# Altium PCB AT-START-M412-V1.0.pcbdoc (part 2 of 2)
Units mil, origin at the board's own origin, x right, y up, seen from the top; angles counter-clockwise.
Board outline 4079.45 x 3617.4 mil, 2 copper layers (Top Layer, Bottom Layer); 111 components, 104 nets, 441 pads, 691 vias.
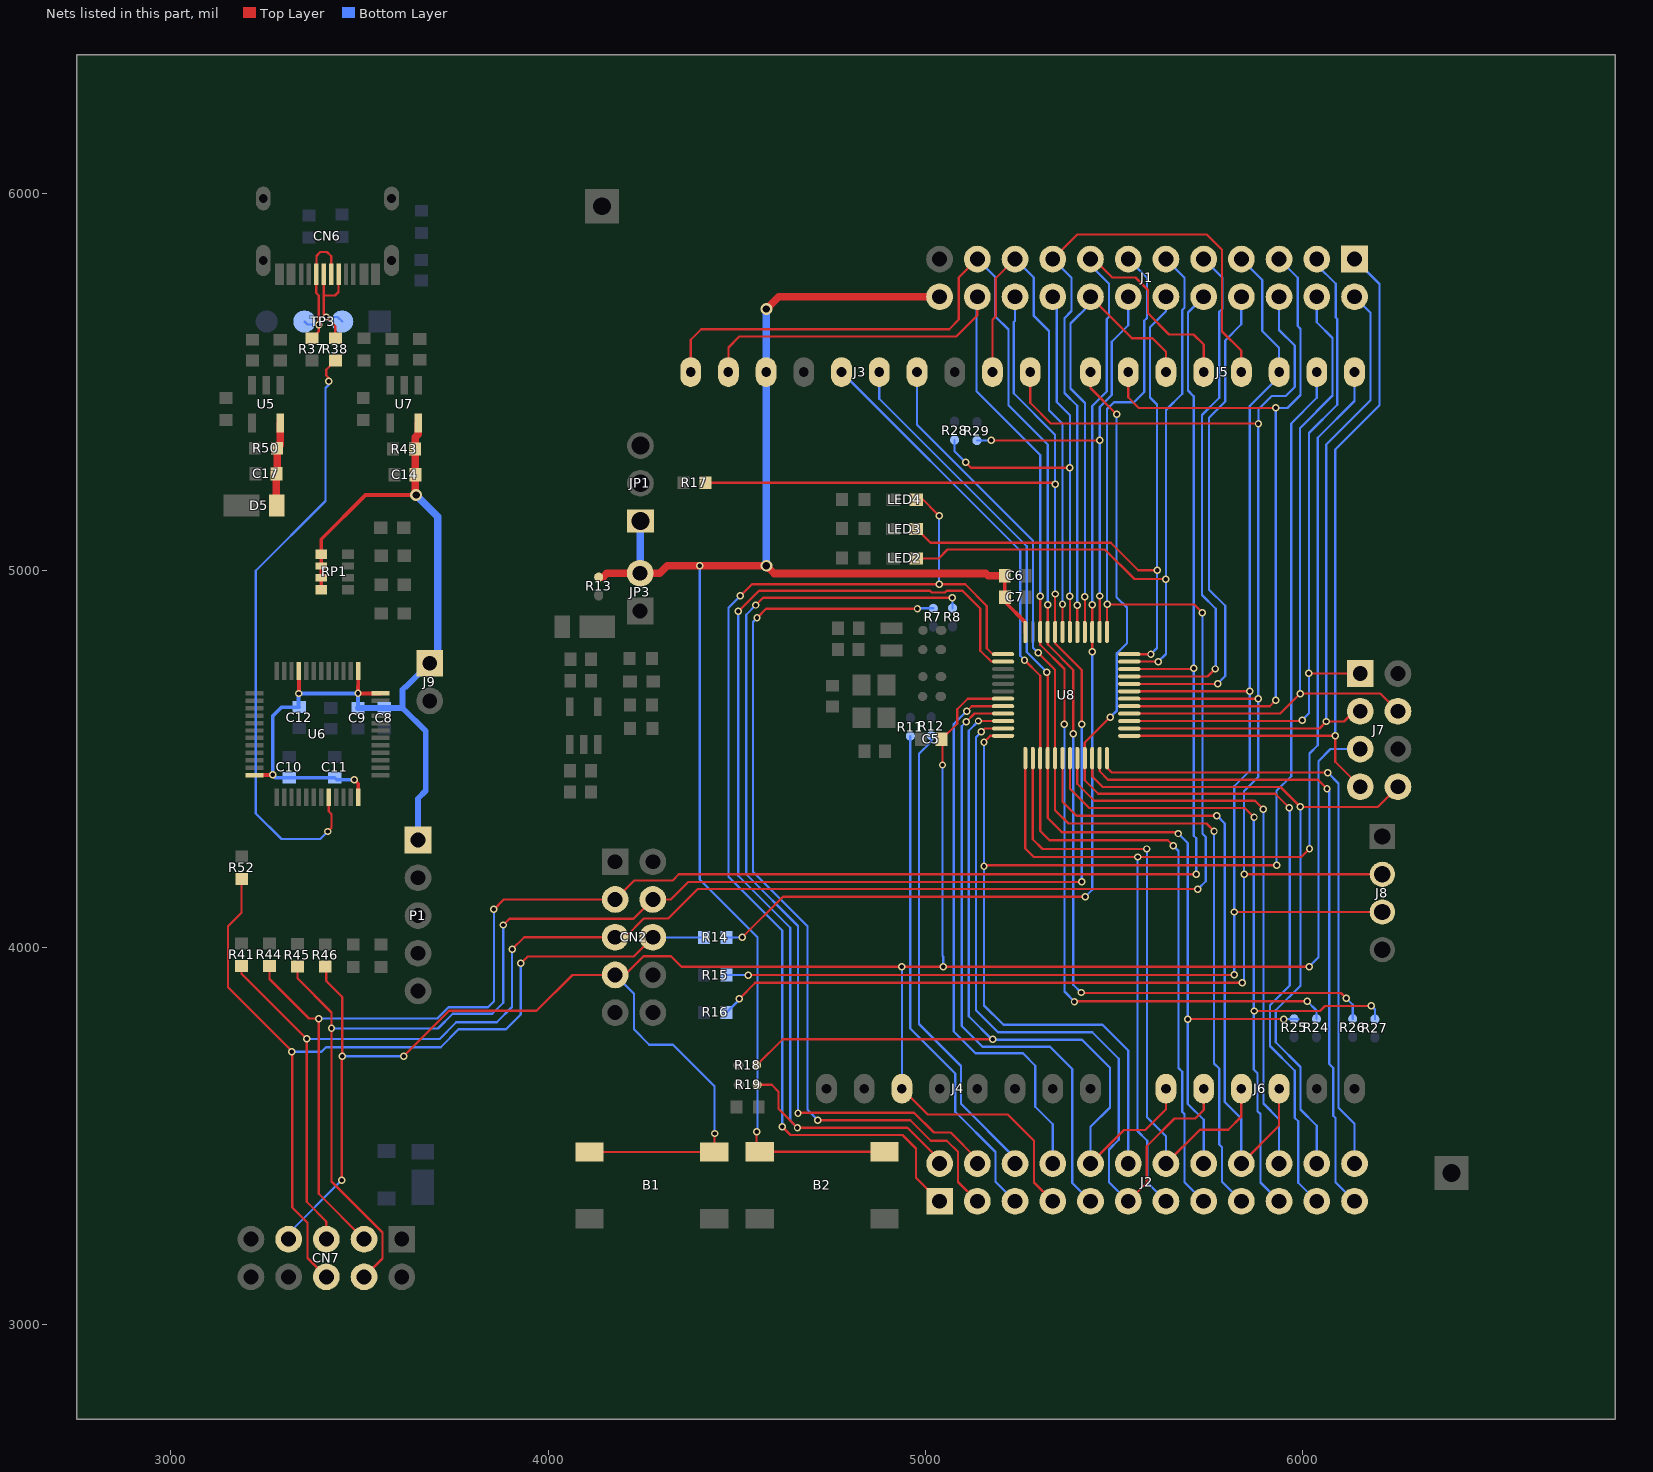
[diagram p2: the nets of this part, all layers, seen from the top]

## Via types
v1: diameter 19.68, hole 11.81, Top Layer to Bottom Layer, 340 vias
v2: diameter 19.7, hole 11.81, Top Layer to Bottom Layer, 266 vias
v3: diameter 19.7, hole 11.8, Top Layer to Bottom Layer, 67 vias
v4: diameter 31.5, hole 19.68, Top Layer to Bottom Layer, 18 vias

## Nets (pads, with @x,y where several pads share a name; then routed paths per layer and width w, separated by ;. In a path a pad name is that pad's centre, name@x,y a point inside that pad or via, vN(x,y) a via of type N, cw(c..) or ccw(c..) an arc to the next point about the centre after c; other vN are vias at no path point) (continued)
M-USB_DM: R38.2 U6.32 | length 1617.9
  Top Layer w6: v2(3415.92,4307.82) 3425.78,4317.68 3425.78,4353.69 3418.1,4361.38 U6.32@3418.1,4398.38 ; v2(3417.92,5501.82) 3417.92,5510.87 3411.92,5516.87 3411.92,5532.16 R38.2@3435.92,5556.16
  Bottom Layer w6: v2(3415.92,4307.82) 3395.92,4287.82 3292.9,4287.82 3225.1,4355.61 3225.1,4998.99 3409.92,5183.82 3409.92,5483.82 3417.92,5491.82 v2(3417.92,5501.82)
M-USB_DP: 
NRST/PF2: B1.1 B1.2 C5.2 CN2.7 CN7.7 J2.7 J4.3 J7.5 R46.2 U8.7 | length 6851
  Top Layer w6: R46.2@3409.1,3947.03 3412.1,3944.03 3412.1,3911.15 3453.92,3869.33 v2(3453.92,3712.19) 3452.74,3711.01 v2(3452.74,3383.56) ; v1(3616.76,3711.99) 3737.05,3832.28 3969.28,3832.28 4064.53,3927.53 CN2.7@4177.67,3927.53 4203.13,3927.53 4252.77,3977.17 4326.06,3977.17 4353.93,3949.29 v1@4938.05,3949.29 ; B1.1@4110.01,3458.22 B1.2@4440.71,3458.22 4441.21,3458.72 v3(4441.21,3507.15) ; J4.3@4937.93,3625.82 5006.53,3557.21 5218.78,3557.21 5287.94,3488.05 5287.94,3377.38 J2.7@5337.93,3327.39 ; v1(4937.93,3949.17) v1@4938.05,3949.29 ; v3(5045.56,4484.05) 5045.56,4549.51 C5.2@5043.05,4552.03 5084.66,4593.63 5084.66,4632.06 5112.4,4659.79 U8.7@5206.24,4659.79 ; v1@6013.68,3949.29 v3(5047.61,3949.29) v1@4938.05,3949.29
  Bottom Layer w6: CN7.7@3312.1,3227.03 3312.1,3242.91 v2(3452.74,3383.56) ; v2(3453.92,3712.19) 3616.56,3712.19 v1(3616.76,3711.99) ; CN2.7@4177.67,3927.53 4227.41,3877.79 4227.41,3783.2 4268.13,3742.48 4330.94,3742.48 4441.21,3632.2 v3(4441.21,3507.15) ; J4.3@4937.93,3625.82 v1(4937.93,3949.17) ; v3(5045.56,4484.05) 5045.56,3978.74 5047.82,3976.48 5047.82,3949.29 v3(5047.61,3949.29) ; v1(6017.36,3949.51) 6042.24,3974.39 6042.24,4494.23 6074.39,4526.39 J7.5@6152.93,4526.39
PA0: J2.10 J6.1 R18.1 U8.10 | length 2535.9
  Top Layer w6: R18.1@4552.67,3688.08 4621.93,3757.34 v3(5178.41,3757.34) ; v1(5140.91,4600.69) U8.10@5206.24,4600.69 ; J2.10@5437.93,3427.39 5526.91,3516.37 5583.1,3516.37 5637.93,3571.19 J6.1@5637.93,3625.82
  Bottom Layer w6: v1(5140.91,4600.69) 5114.9,4574.68 5114.9,3818.16 5178.05,3755.01 v3@5178.41,3755.38 ; v3(5178.41,3757.34) v3@5178.41,3755.38 ; J2.10@5437.93,3427.39 5437.93,3524.74 5489.42,3576.23 5489.42,3681.18 5415.22,3755.38 v3@5178.41,3755.38
PA1: J2.11 J6.2 U8.11 | length 2060.1
  Top Layer w6: v1(5148.24,4571.84) 5157.39,4580.99 U8.11@5206.24,4580.99 ; J2.11@5537.93,3327.39 5587.23,3376.7 5587.23,3473.4 5660.76,3546.92 5715.38,3546.92 5737.93,3569.46 J6.2@5737.93,3625.82
  Bottom Layer w6: v1(5148.24,4571.84) 5134.38,4557.98 5134.38,3833.78 5192.69,3775.48 5442.56,3775.48 5513.01,3705.02 5513.01,3490.3 5487.21,3464.5 5487.21,3378.11 J2.11@5537.93,3327.39
PA2: J2.12 J5.2 U8.12 | length 3615.6
  Top Layer w6: v1(5155.54,4544.83) 5172,4561.29 U8.12@5206.24,4561.29 ; v1(5155.64,4216.06) 5158.01,4218.43 v1(5931.14,4218.43)
  Bottom Layer w6: v1(5155.54,4544.83) v1@5155.54,4216.06 ; v1(5155.64,4216.06) v1@5155.54,4216.06 ; J2.12@5537.93,3427.39 5537.93,3727.28 5470.06,3795.15 5207.02,3795.15 5155.54,3846.64 v1@5155.54,4216.06 ; v1(5931.14,4218.43) 5931.14,4415.58 5970.01,4454.45 5970.01,5389.55 6037.93,5457.47 J5.2@6037.93,5525.82
PA3: J2.13 J5.1 U8.13 | length 3269.1
  Top Layer w6: U8.13@5265.24,4502.29 5265.24,4262.51 5287.79,4239.96 v1@5562.51,4239.96 ; v1(5562.69,4240.14) v1@5562.51,4239.96 ; v1(6018.57,4262.12) 5996.41,4239.96 v1@5562.51,4239.96
  Bottom Layer w6: v1(5562.69,4240.14) 5562.47,4239.92 5562.47,3513.58 5588.15,3487.9 5588.15,3377.18 J2.13@5637.93,3327.39 ; v1(6018.57,4262.12) 6018.57,4514.82 6040.14,4536.38 6040.14,5351.42 6137.93,5449.2 J5.1@6137.93,5525.82
PA4: J2.14 J6.3 U8.14 | length 1708.5
  Top Layer w6: U8.14@5284.94,4502.29 5284.94,4287.26 5310.73,4261.47 v1(5587.21,4261.47) ; J2.14@5637.93,3427.39 5727.92,3517.39 5803.28,3517.39 5837.93,3552.03 J6.3@5837.93,3625.82
  Bottom Layer w6: v1(5587.21,4261.47) 5587.68,4261.01 5587.68,3549.98 5637.93,3499.74 J2.14@5637.93,3427.39
PA5: J2.15 J3.6 U8.15 | length 2779.8
  Top Layer w6: v1(5262.99,4762.21) 5304.64,4720.55 U8.15@5304.64,4502.29 5304.64,4309.03 5329.11,4284.57 5642.7,4284.57 v1(5657.69,4269.58)
  Bottom Layer w6: J3.6@4777.93,5525.82 5251.54,5052.21 5251.54,4773.66 v1(5262.99,4762.21) ; v1(5657.69,4269.58) 5671.38,4255.89 5671.38,3680.63 5681.12,3670.88 5681.12,3564.97 5687.43,3558.67 5687.43,3377.89 J2.15@5737.93,3327.39
PA6: J2.16 J3.5 R25.1 U8.16 | length 2926.7
  Top Layer w6: v1(5322.25,4730.35) 5324.34,4728.26 U8.16@5324.34,4502.29 5324.34,4343.73 5361.93,4306.14 5667.09,4306.14 v1(5670.82,4302.41) ; v3(5696.26,3810.24) 5696.43,3810.42 v3(5949.99,3810.42)
  Bottom Layer w6: J3.5@4877.93,5525.82 4877.93,5455.38 5268.99,5064.32 5268.99,4783.61 v1(5322.25,4730.35) ; v1(5670.82,4302.41) 5695.62,4277.61 v3@5695.62,3810.65 ; v3(5696.26,3810.24) 5696.02,3810.24 v3@5695.62,3810.65 ; J2.16@5737.93,3427.39 5737.93,3543.27 5695.62,3585.58 v3@5695.62,3810.65 ; v3(5949.99,3810.42) 5988.44,3810.42 R25.1@5988.61,3810.24
PA7: J2.17 J3.4 U8.17 | length 2769
  Top Layer w6: v1(5299.64,4781.17) 5344.04,4736.77 U8.17@5344.04,4502.29 5344.04,4364.42 5379.71,4328.75 5745.63,4328.75 v1(5765.44,4308.94)
  Bottom Layer w6: J3.4@4977.93,5525.82 4977.93,5386.12 5285.71,5078.34 5285.71,4795.1 v1(5299.64,4781.17) ; v1(5765.44,4308.94) 5765.44,3692.91 5778.99,3679.36 5778.99,3478.08 5786.43,3470.64 5786.43,3378.89 J2.17@5837.93,3327.39
PA8: J1.5 J5.7 U8.29 | length 2103.5
  Top Layer w6: J5.7@5537.93,5525.82 5537.93,5458.76 5565.91,5430.77 v1(5929.53,5430.77) ; U8.29@5540.84,4640.09 5913.32,4640.09 v1(5929.04,4655.82)
  Bottom Layer w6: v1(5929.04,4655.82) 5929.04,5430.28 v1(5929.53,5430.77) 5960.36,5430.77 5994.76,5465.17 5994.76,5640.27 5987.32,5647.71 5987.32,5776.08 J1.5@5937.91,5825.49
PA9/USART1_TX: J1.6 J3.1 J8.2 R16.1 U8.30 | length 4727.5
  Top Layer w6: v3(4507.15,3864.57) 4549.44,3906.86 5840.33,3906.86 v1(5840.33,3906.52) ; J3.1@5277.93,5525.82 5277.93,5444.15 5332.77,5389.3 v1(5883.24,5389.3) ; U8.30@5540.84,4659.79 5882.41,4659.79 v1(5882.65,4660.03) ; v3(5845.04,4194.37) J8.2@6211.54,4194.37
  Bottom Layer w6: R16.1@4473.12,3828.11 v3@4503.24,3858.23 ; v1(5840.33,3906.52) 5844.99,3911.18 v3(5845.04,4194.37) 5844.99,4414.48 5882.65,4452.14 v1(5882.65,4660.03) 5882.65,5388.71 v1(5883.24,5389.3) 5883.24,5427.11 5918.5,5462.37 5955.89,5462.37 5979.46,5485.94 5979.46,5596.05 5937.91,5637.6 J1.6@5937.91,5725.49
PA10/USART1_RX: J1.7 J5.3 J8.3 R15.1 U8.31 | length 4046.6
  Top Layer w6: v1(4530.17,3927.07) 5818.51,3927.07 v1(5818.99,3927.55) ; U8.31@5540.84,4679.39 5859.69,4679.39 v1(5859.85,4679.55) ; v3@5819.24,4094.37 J8.3@6211.54,4094.37
  Bottom Layer w6: R15.1@4472.76,3927.07 v1(4530.17,3927.07) ; v1(5818.99,3927.55) v3@5818.99,4094.33 ; v3(5819.2,4094.33) v3@5818.99,4094.33 ; J1.7@5837.91,5825.49 5893.48,5769.93 5893.48,5634.72 5937.93,5590.27 J5.3@5937.93,5525.82 5937.93,5513.63 5859.85,5435.55 v1(5859.85,4679.55) 5859.85,4468.91 5818.99,4428.06 v3@5818.99,4094.33
PA11: J1.8 U8.32 | length 1321.6
  Top Layer w6: U8.32@5540.84,4699.09 5774.09,4699.09 v1(5774.78,4699.78)
  Bottom Layer w6: v1(5774.78,4699.78) 5795.04,4720.05 5795.04,4906.01 5752.13,4948.92 5752.13,5404.96 5795.04,5447.87 5795.04,5609.74 5837.91,5652.61 J1.8@5837.91,5725.49
PA12: J1.9 U8.33 | length 1381.3
  Top Layer w6: U8.33@5540.84,4718.79 5748.35,4718.79 v1(5768.23,4738.67)
  Bottom Layer w6: J1.9@5737.91,5825.49 5787.67,5775.73 5787.67,5693.85 5779.51,5685.69 5779.51,5458 5733.53,5412.02 5733.53,4934.98 5770.01,4898.49 5770.01,4740.45 v1@5768.29,4738.73
PA13/SWDIO: CN2.3 CN7.3 J1.10 R44.2 U8.34 | length 5200
  Top Layer w6: R44.2@3261.3,3951.41 3261.3,3916.44 3365.92,3811.82 v2(3391.92,3811.82) 3391.92,3347.2 CN7.3@3512.1,3227.03 ; v2(3856.23,4101.13) 3882.63,4127.53 CN2.3@4177.67,4127.53 4228.3,4178.15 4330.17,4178.15 4346.4,4194.38 v1(5718.32,4194.38) ; U8.34@5540.84,4738.49 5709.8,4738.49 v1(5711.64,4740.33)
  Bottom Layer w6: v2(3391.92,3811.82) 3705.89,3811.82 3735.97,3841.9 3840.32,3841.9 3856.23,3857.81 v2(3856.23,4101.13) ; v1@5711.58,4740.38 5711.58,5461.35 5696.16,5476.77 5696.16,5683.74 J1.10@5737.91,5725.49 ; v1(5711.64,4740.33) 5711.64,4296.69 5718.32,4290 v1(5718.32,4194.38)
PA14/SWCLK: CN2.5 CN7.5 J1.13 R41.2 U8.37 | length 5525.2
  Top Layer w6: R41.2@3187.3,3951.41 3187.3,3930.44 v2(3359.92,3757.82) 3359.92,3326.08 3412.1,3273.9 CN7.5@3412.1,3227.03 ; v2(3904.53,3995.38) 3936.68,4027.53 CN2.5@4177.67,4027.53 4204.22,4027.53 4253.74,4077.05 4318.57,4077.05 4396.59,4155.07 v1@5722.61,4155.07 ; U8.37@5481.84,4836.89 v1(5481.84,4909.82) 5712.77,4909.82 v1(5734.67,4887.91)
  Bottom Layer w6: v2(3359.92,3757.82) 3712.75,3757.82 3756.74,3801.81 3863.54,3801.81 3904.53,3842.8 v2(3904.53,3995.38) ; v1(5481.84,4909.82) 5481.84,5427.57 5499.95,5445.69 5553.32,5445.69 5580.44,5472.8 5580.44,5661.67 5587.65,5668.88 5587.65,5775.76 J1.13@5537.91,5825.49 ; v1(5722.61,4155.05) 5743.17,4175.61 5743.17,4293.27 5734.67,4301.77 v1(5734.67,4887.91)
PA15: J1.14 R29.1 U8.38 | length 1245.1
  Top Layer w6: v1(5174.93,5344.52) v1(5462.07,5344.52) ; U8.38@5462.14,4836.89 v1(5462.14,4932.14)
  Bottom Layer w6: R29.1@5136.87,5344.52 v1(5174.93,5344.52) ; v1(5462.14,4932.14) v1(5462.07,5344.52) ; v1@5462.14,5344.59 5462.14,5433.06 5494.14,5465.06 5494.14,5606.27 5537.91,5650.04 J1.14@5537.91,5725.49
PB0: J2.18 J6.4 U8.18 | length 1729.3
  Top Layer w6: U8.18@5363.74,4502.29 5363.74,4386.84 5400.71,4349.86 v1(5773.13,4349.89) ; J2.18@5837.93,3427.39 5937.93,3527.39 J6.4@5937.93,3625.82
  Bottom Layer w6: v1(5773.13,4349.89) 5793.76,4329.26 5793.76,3590.68 5837.93,3546.51 J2.18@5837.93,3427.39
PB1: J2.19 R27.1 U8.19 | length 2003.4
  Top Layer w6: U8.19@5383.34,4502.29 5383.34,4421.23 5434.64,4369.93 5846.96,4369.93 v1(5871.45,4345.43) ; v3(5872.22,3831.92) 6046.43,3831.92 6059.93,3845.41 v3(6182.55,3845.41)
  Bottom Layer w6: v1(5871.45,4345.43) 5870.77,4344.75 v3@5870.77,3831.92 ; v3(5872.22,3831.92) v3@5870.77,3831.92 ; J2.19@5937.93,3327.39 5888.39,3376.93 5888.39,3558.75 5880.7,3566.44 5880.7,3666.77 5870.77,3676.7 v3@5870.77,3831.92 ; v3(6182.55,3845.41) 6192.02,3835.94 R27.1@6192.02,3810.08
PB2: J2.20 U8.20 | length 1545.8
  Top Layer w6: U8.20@5403.04,4502.29 5403.04,4434.24 5447.99,4389.29 5873.72,4389.29 v1(5895.67,4367.33)
  Bottom Layer w6: v1(5895.67,4367.33) 5896.29,4366.72 5896.29,3586.81 5937.93,3545.16 J2.20@5937.93,3427.39
PB3/SWO: J1.15 J5.5 R14.1 U8.39 | length 3236
  Top Layer w6: v3(4514.86,4027.13) 4622.69,4134.96 v3(5423.96,4134.96) ; J1.15@5437.91,5825.49 5446.38,5825.49 5495.43,5776.43 5557.4,5776.43 5590.45,5743.38 5590.45,5681.42 5646.22,5625.64 5710.95,5625.64 5737.93,5598.66 J5.5@5737.93,5525.82 ; v1(5442.44,4784.01) U8.39@5442.44,4836.89 v1(5442.44,4909.13)
  Bottom Layer w6: R14.1@4472.73,4026.98 4514.71,4026.98 v3(4514.86,4027.13) ; v3(5423.96,4134.96) 5442.44,4153.44 v1(5442.44,4784.01) ; J1.15@5437.91,5825.49 5437.91,5808.94 5486.88,5759.97 5486.88,5672.32 5480.88,5666.32 5480.88,5474.43 5442.44,5435.99 v1(5442.44,4909.13)
PB4: J1.16 J5.6 U8.40 | length 1240.8
  Top Layer w6: U8.40@5422.74,4836.89 5423.15,4837.3 v1@5423.15,4930.45 ; J1.16@5437.91,5725.49 5547.59,5615.81 5601.93,5615.81 5637.93,5579.82 J5.6@5637.93,5525.82
  Bottom Layer w6: v1(5423.16,4930.46) 5423.16,5444 5385.07,5482.09 5385.07,5654.4 5437.91,5707.24 J1.16@5437.91,5725.49
PB5: J1.17 J5.4 U8.41 | length 1869.6
  Top Layer w6: J1.17@5337.91,5825.49 5403.07,5890.65 5746.37,5890.65 5786.65,5850.37 5786.65,5633.49 5837.93,5582.21 J5.4@5837.93,5525.82 ; U8.41@5403.04,4836.89 v1(5403.03,4907.98)
  Bottom Layer w6: J1.17@5337.91,5825.49 5387.86,5775.54 5387.86,5687.67 5368.76,5668.56 5368.76,5470.53 5403.03,5436.26 v1(5403.03,4907.98)
PB6: J1.18 R28.1 U8.42 | length 1261
  Top Layer w6: v1(5106.66,5286.81) 5121.14,5272.33 v3(5383.33,5272.33) ; U8.42@5383.34,4836.89 v1(5383.33,4931.47)
  Bottom Layer w6: R28.1@5077.61,5345.73 5077.61,5315.86 v1(5106.66,5286.81) ; J1.18@5337.91,5725.49 5348.6,5714.8 5348.6,5446.31 5383.33,5411.58 v3(5383.33,5272.33) v1(5383.33,4931.47)
PB7: J1.19 J3.2 U8.43 | length 1365.2
  Top Layer w6: J3.2@5177.93,5525.82 5177.93,5664.32 5187.01,5673.4 5187.01,5774.59 J1.19@5237.91,5825.49 ; U8.43@5363.74,4836.89 v2(5363.74,4910.56)
  Bottom Layer w6: J1.19@5237.91,5825.49 5287.82,5775.59 5287.82,5674.47 5327.64,5634.65 5327.64,5424.76 5363.74,5388.66 v2(5363.74,4910.56)
PB8: J1.21 J3.10 R26.1 U8.45 | length 3828.6
  Top Layer w6: J3.10@4377.93,5525.82 4377.93,5611.25 4406.23,5639.55 5063.23,5639.55 5088.64,5664.96 5088.64,5776.22 J1.21@5137.91,5825.49 ; v2(5324.34,4909.04) U8.45@5324.34,4836.89 5324.34,4804.29 5392.43,4736.19 v1(5392.43,4567.27) ; v3(5413.07,3880.89) 5414.07,3879.89 6101.81,3879.89 v1(6115.84,3865.85)
  Bottom Layer w6: J1.21@5137.91,5825.49 5185.54,5777.86 5185.54,5673.33 5220.26,5638.61 5220.26,5437.7 5324.34,5333.62 v2(5324.34,4909.04) ; v1(5392.43,4567.27) 5392.43,3901.52 v3(5413.07,3880.89) ; v1(6115.84,3865.85) 6133.09,3848.61 R26.1@6133.09,3811.31
PB9: J1.22 J3.9 R24.1 U8.46 | length 3466.3
  Top Layer w6: J3.9@4477.93,5525.82 4477.93,5591.17 4506.72,5619.96 5082.29,5619.96 5137.91,5675.58 J1.22@5137.91,5725.49 ; v2(5304.64,4931.39) U8.46@5304.64,4836.89 5304.64,4802.85 5368.76,4738.73 v1(5368.76,4591.97) ; v3@5390.68,3857.79 v1(6012.72,3857.79)
  Bottom Layer w6: J1.22@5137.91,5725.49 5135.73,5723.31 5135.73,5474.99 5304.64,5306.08 v2(5304.64,4931.39) ; v1(5368.76,4591.97) 5368.76,3883.41 v3(5395.42,3856.75) ; v1(6012.72,3857.79) 6036.99,3833.53 R24.1@6036.99,3810.98
PB10: J2.21 J5.8 U8.21 | length 2858.2
  Top Layer w6: J5.8@5437.93,5525.82 5437.93,5483.4 v1(5507.1,5414.23) ; v1(5490.29,4611.12) 5422.74,4543.58 U8.21@5422.74,4502.29 5422.74,4443.53 5458.51,4407.76 5928.04,4407.76 v1(5964.81,4370.99)
  Bottom Layer w6: v1(5490.29,4611.12) 5507.87,4628.69 5507.87,4780.3 5534.57,4807.01 5534.57,4901.66 5507.1,4929.13 v1(5507.1,5414.23) ; v1(5964.81,4370.99) 5966.24,4369.56 5966.24,3899.41 5913.69,3846.87 5913.69,3739.36 5979.61,3673.44 5979.61,3548.48 5988.43,3539.67 5988.43,3376.9 J2.21@6037.93,3327.39
PB11: J2.22 J7.8 U8.22 | length 1932.1
  Top Layer w6: U8.22@5442.44,4502.29 5442.44,4453.78 5470.27,4425.95 5941.33,4425.95 v1(5994.4,4372.87) ; v1(5994.4,4372.87) 6199.42,4372.89 J7.8@6252.93,4426.39
  Bottom Layer w6: v1@5994.46,4372.81 5994.46,3899.06 5929.22,3833.82 5929.22,3749.01 5994.46,3683.76 5994.46,3571.01 6037.93,3527.55 J2.22@6037.93,3427.39
PB12: J1.1 J7.7 U8.25 | length 2048.8
  Top Layer w6: U8.25@5540.84,4561.29 6086.53,4561.29 v1(6086.93,4561.69) 6086.93,4492.39 J7.7@6152.93,4426.39
  Bottom Layer w6: v1(6086.93,4561.69) 6086.45,4562.17 6086.45,5320.09 6203.87,5437.51 6203.87,5759.53 J1.1@6137.91,5825.49
PB13: J1.2 J7.3 U8.26 | length 1823.3
  Top Layer w6: U8.26@5540.84,4580.99 6044.85,4580.99 v1@6063.05,4599.19 ; v1(6063.05,4599.46) v1@6063.05,4599.19 ; J7.3@6152.93,4626.39 6137.09,4626.39 6109.89,4599.19 v1@6063.05,4599.19
  Bottom Layer w6: v1(6063.05,4599.46) 6063.05,5333.83 6180.29,5451.07 6180.29,5683.11 J1.2@6137.91,5725.49
PB14: J1.3 J7.1 U8.27 | length 1878.8
  Top Layer w6: U8.27@5540.84,4600.69 5996.84,4600.69 v2(5998.91,4602.76) ; v1(6016.96,4726.8) 6152.52,4726.8 J7.1@6152.93,4726.39
  Bottom Layer w6: v2(5998.91,4602.76) 6017.45,4621.3 6017.45,5364.43 6092,5438.98 6092,5666.21 6087.87,5670.34 6087.87,5759.85 6037.91,5809.81 J1.3@6037.91,5825.49
PB15: J1.4 J7.4 U8.28 | length 1859
  Top Layer w6: U8.28@5540.84,4620.39 5941.08,4620.39 v2(5994.16,4673.47) 6205.85,4673.47 J7.4@6252.93,4626.39
  Bottom Layer w6: v2(5994.16,4673.47) 5993.32,4674.31 5993.32,5377.03 6079.67,5463.37 6079.67,5616.2 6037.91,5657.96 J1.4@6037.91,5725.49
PC13: J2.2 R19.1 U8.2 | length 2908.6
  Top Layer w6: v1(4504.06,4891.23) 4558.87,4946.05 5012.17,4946.05 5016.78,4941.44 5052.48,4941.44 5057.08,4946.05 5098.64,4946.05 5145.95,4898.74 5145.95,4786.73 5174.48,4758.19 U8.2@5206.24,4758.19 ; R19.1@4554.12,3636.15 4592.67,3636.15 4610.95,3617.87 4610.95,3572.61 v3(4661.08,3522.48) 4952.99,3522.48 5037.93,3437.54 J2.2@5037.93,3427.39
  Bottom Layer w6: v1(4504.06,4891.23) 4504.06,4190.77 4642.03,4052.8 4642.03,3541.52 v3(4661.08,3522.48)
PC14: J2.3 R7.1 | length 2444
  Top Layer w6: v1(4553.75,4874.09) 4577.95,4898.29 v1(4979.22,4898.29) ; v3@4714.6,3542.6 4960.01,3542.6 5014.54,3488.07 5056.92,3488.07 5086.53,3458.45 5086.53,3378.79 J2.3@5137.93,3327.39
  Bottom Layer w6: v1(4553.75,4874.09) 4543.09,4863.43 4543.09,4201.14 4687.39,4056.84 4687.39,3569.81 v3(4714.55,3542.65) ; v1(4979.22,4898.29) 4980.24,4899.31 R7.1@5021.33,4899.31
PC15: J2.4 R8.1 | length 2509.9
  Top Layer w6: v3(4550.57,4908.19) 4569.58,4927.2 v3(5071.75,4927.2) ; v3(4662.47,3561.03) 4663.7,3562.26 4969.96,3562.26 5022.73,3509.5 5067.31,3509.5 5137.93,3438.87 J2.4@5137.93,3427.39
  Bottom Layer w6: v3(4550.57,4908.19) 4525.1,4882.71 4525.1,4194.43 4662.47,4057.06 v3(4662.47,3561.03) ; v3(5071.75,4927.2) 5072.35,4926.6 R8.1@5072.35,4899.75
PF0: J2.5 R11.1 | length 1348.3
  Bottom Layer w6: R11.1@4960.34,4560.75 4960.34,3785.54 5079.4,3666.48 5079.4,3564.75 5186.14,3458.01 5186.14,3379.19 J2.5@5237.93,3327.39
PF1: J2.6 R12.1 | length 1253.9
  Bottom Layer w6: R12.1@5015.44,4562.24 5015.44,4546.04 4983,4513.6 4983,3797.51 5094.39,3686.12 5094.39,3585.74 5237.93,3442.21 J2.6@5237.93,3427.39
PF6: J1.11 LED2.2 U8.35 | length 1897.5
  Top Layer w6: LED2.2@4976.02,5031.75 5035.39,5031.75 5058.88,5055.24 5476.03,5055.24 5554.26,4977.01 v1(5637.45,4977.01) ; U8.35@5540.84,4758.19 5540.93,4758.28 v1(5617.84,4758.28)
  Bottom Layer w6: v1(5617.84,4758.28) 5637.91,4778.35 v1@5637.91,4977.01 ; v1(5637.45,4977.01) v1@5637.91,4977.01 ; J1.11@5637.91,5825.49 5687.32,5776.08 5687.32,5696.41 5681.32,5690.41 5681.32,5468.34 5637.91,5424.94 v1@5637.91,4977.01
PF7: J1.12 LED3.2 U8.36 | length 1719.9
  Top Layer w6: LED3.2@4977.17,5109.75 5013.51,5073.41 5491.8,5073.41 5564.57,5000.63 v1(5614.56,5000.63) ; U8.36@5540.84,4777.89 v1(5598.24,4777.89)
  Bottom Layer w6: v1(5598.24,4777.89) 5614.36,4794.01 v1@5614.36,5000.63 ; v1(5614.56,5000.63) v1@5614.36,5000.63 ; J1.12@5637.91,5725.49 5637.91,5687.06 5595.46,5644.61 5595.46,5458.7 5614.36,5439.8 v1@5614.36,5000.63
PF8: J2.1 LED4.2 U8.1 | length 3139
  Top Layer w6: v3(4509.76,4932.49) 4540.22,4962.95 v1@5036.16,4962.95 ; v3(4621.06,3524.68) 4642.55,3503.19 4939.57,3503.19 4975.52,3467.24 4975.52,3389.8 J2.1@5037.93,3327.39 ; LED4.2@4975.17,5193.75 4987.88,5193.75 v1(5036.42,5145.21) ; v1(5036.46,4963.25) v1@5036.16,4962.95 ; U8.1@5206.24,4777.89 5179.04,4777.89 5163.1,4793.84 5163.1,4905.54 5105.69,4962.95 v1@5036.16,4962.95
  Bottom Layer w6: v3(4509.76,4932.49) 4478.09,4900.82 4478.09,4187.99 4620.91,4045.17 4620.91,3524.82 v3(4621.06,3524.68) ; v1@5036.42,4963.3 v1(5036.42,5145.21)
PF9: J2.8 U8.8 | length 1497.7
  Top Layer w6: v1(5110.07,4627.07) 5123.1,4640.09 U8.8@5206.24,4640.09
  Bottom Layer w6: v1(5110.07,4627.07) 5075.63,4592.63 5075.63,3777.27 5133.2,3719.7 5258.68,3719.7 5291.73,3686.65 5291.73,3577.95 5337.93,3531.75 J2.8@5337.93,3427.39
PF10: J2.9 U8.9 | length 1629
  Top Layer w6: v1(5108.82,4598.77) 5130.45,4620.39 U8.9@5206.24,4620.39
  Bottom Layer w6: v1(5108.82,4598.77) 5096.58,4586.52 5096.58,3791.9 5151.56,3736.92 5330.5,3736.92 5389.33,3678.08 5389.33,3375.99 J2.9@5437.93,3327.39
PF11/BOOT0: CN2.4 CN7.4 J1.20 R17.1 R45.2 U8.44 | length 5763.8
  Top Layer w6: R45.2@3335.3,3950.41 3335.3,3918.44 3425.75,3827.99 v2(3425.75,3786.09) 3425.75,3379.85 3561.08,3244.52 3561.08,3176.01 CN7.4@3512.1,3127.03 ; v2(3880.98,4059.92) 3897.47,4076.4 4226.55,4076.4 CN2.4@4277.67,4127.53 4325.08,4127.53 4371.56,4174.01 v1(5415.03,4174.01) ; R17.1@4417.63,5232.49 5339.97,5232.49 v3(5343.97,5228.49) ; v1(5344.04,4937.45) U8.44@5344.04,4836.89 5344.04,4806.67 5414.9,4735.81 v1(5414.9,4591.73)
  Bottom Layer w6: v2(3425.75,3786.09) 3426.02,3785.82 3708.2,3785.82 3746.83,3824.45 3851.6,3824.45 3880.98,3853.84 v2(3880.98,4059.92) ; J1.20@5237.91,5725.49 5237.91,5661.1 5234.44,5657.63 5234.44,5469.51 5344.04,5359.91 v3(5343.97,5228.49) v1(5344.04,4937.45) ; v1(5414.9,4591.73) 5414.9,4174.14 v1(5415.03,4174.01)
PF12: J2.23 U8.23 | length 1781
  Top Layer w6: U8.23@5462.14,4502.29 5462.14,4467.39 5484.43,4445.09 6041.24,4445.09 v1(6064.98,4421.35)
  Bottom Layer w6: v1(6064.98,4421.35) 6070.55,4415.78 6070.55,3692.19 6081.77,3680.97 6081.77,3554.41 6087.24,3548.94 6087.24,3378.08 J2.23@6137.93,3327.39
PF13: J2.24 U8.24 | length 1681.9
  Top Layer w6: U8.24@5481.84,4502.29 5481.84,4476.65 5494.57,4463.92 v1(6066.91,4463.92)
  Bottom Layer w6: v1(6066.91,4463.92) 6095.5,4435.32 6095.5,3575.53 6137.93,3533.1 J2.24@6137.93,3427.39
SWO: CN2.6 CN7.6 R14.2 R52.2 | length 2478
  Top Layer w6: R52.2@3187.92,4182.16 3187.1,4181.33 3187.1,4092.43 3151.16,4056.49 3151.16,3894.58 v1@3320.82,3724.92 ; v1(3320.21,3724.11) 3320.21,3724.31 v1@3320.82,3724.92 ; CN7.6@3412.1,3127.03 3361.98,3177.14 3361.98,3270.73 3321.92,3310.79 3321.92,3723.82 v1@3320.82,3724.92 ; v1(3927.59,3958.11) 3946.18,3976.7 4226.84,3976.7 CN2.6@4277.67,4027.53
  Bottom Layer w6: v1(3320.21,3724.11) 3399.2,3724.11 3411.15,3736.05 3715.25,3736.05 3762.43,3783.23 3888.29,3783.23 3927.59,3822.53 v1(3927.59,3958.11) ; CN2.6@4277.67,4027.53 4278.22,4026.98 R14.2@4413.41,4026.98
USBM: CN6.A7 CN6.B7 R38.1 TP3.2 | length 320.3
  Top Layer w6: CN6.A7@3405.12,5785.52 3405.12,5728.88 ; R38.1@3435.92,5615.48 3435.92,5647.82 v2(3411.92,5671.82) 3405.12,5678.62 3405.12,5728.88 ; CN6.B7@3444.42,5785.52 3444.42,5738.13 3435.17,5728.88 3405.12,5728.88
  Bottom Layer w6: v2(3411.92,5671.82) 3441.93,5671.82 TP3.2@3453.92,5659.82
USBP: CN6.A6 CN6.B6 R37.1 TP3.3 | length 364.9
  Top Layer w6: R37.1@3373.92,5615.48 3391.92,5633.48 v2(3391.92,5651.82) 3391.92,5728.86 3385.42,5735.36 CN6.B6@3385.42,5785.52 3385.92,5786.02 3385.92,5833.82 3395.92,5843.82 3413.92,5843.82 3424.72,5833.02 CN6.A6@3424.72,5785.52
  Bottom Layer w6: TP3.3@3353.92,5659.82 3361.93,5651.82 v2(3391.92,5651.82)
VCC: C8.2 C9.2 C10.2 C11.2 C12.2 C14.2 J9.1 P1.1 R43.1 RP1.1 RP1.2 RP1.3 RP1.4 U6.1 U6.9 U6.24 U6.36 U6.48 U7.5 | length 2731.1
  Top Layer w10: U6.24@3221.25,4457.43 3269.54,4457.43 v1(3269.92,4457.82) ; v2(3338.58,4673.61) 3339.36,4674.39 U6.9@3339.36,4733.03 ; RP1.4@3398.49,4948.58 RP1.3@3398.49,4980.07 RP1.2@3398.49,5011.57 RP1.1@3398.49,5043.06 3398.49,5082.38 3515.92,5199.82 v4(3649.92,5199.82) ; v1(3486.35,4444.77) 3496.84,4434.27 U6.36@3496.84,4398.38 ; U6.1@3496.84,4733.03 3496.84,4692.77 3495.92,4691.85 v2(3495.92,4673.82) 3516.89,4673.82 3517.04,4673.97 U6.48@3555.9,4673.97
  Top Layer w20: v4(3649.92,5199.82) 3648.09,5201.65 C14.2@3648.09,5253.61 3647.58,5254.12 R43.1@3647.58,5321.82 3647.58,5352.57 3655.92,5360.91 U7.5@3655.92,5390.82
  Bottom Layer w10: v1(3486.35,4444.77) 3439.42,4444.77 C11.2@3433.92,4450.26 C10.2@3313.92,4450.26 3277.48,4450.26 v1(3269.92,4457.82) 3269.92,4613.82 3293.48,4637.38 C12.2@3339.92,4637.38 3338.58,4638.72 v2(3338.58,4673.61) 3338.79,4673.82 v2(3495.92,4673.82) C9.2@3495.92,4635.38
  Bottom Layer w15: C9.2@3495.92,4635.38 C8.2@3565.92,4635.38 3612.62,4635.38 3613.92,4634.07 ; P1.1@3655.1,4285.03 3655.1,4394.99 3675.75,4415.65 3675.75,4573.99 3615.67,4634.07 3613.92,4634.07 ; J9.1@3686.1,4754.03 3623.89,4691.82 3621.92,4691.82 3613.92,4683.82 3613.92,4634.07
  Bottom Layer w20: v4(3649.92,5199.82) 3707.92,5141.82 3707.92,4775.85 J9.1@3686.1,4754.03
VCC3.5V: C17.2 D5.2 R50.1 U5.5 | length 223.8
  Top Layer w20: D5.2@3280.67,5171.82 3279.48,5173.01 C17.2@3279.48,5255.82 3281.58,5257.92 R50.1@3281.58,5323.82 3289.92,5332.16 U5.5@3289.92,5390.82
VDD: B2.3 B2.4 C6.2 C7.2 J1.24 J3.8 JP1.1 JP3.2 R13.1 U8.48 | length 4518.6
  Top Layer w6: v3@4401.5,5012.25 4401.74,5012.49 v3(4401.97,5012.49) ; v2(4552.55,3512.19) 4552.55,3467.22 B2.4@4561.2,3458.57 B2.3@4891.91,3458.57
  Top Layer w10: C7.2@5210.73,4929.3 C6.2@5210.73,4985.83 ; C7.2@5210.79,4929.24 5210.79,4916.67 5265.24,4862.22 U8.48@5265.24,4836.89
  Top Layer w20: R13.1@4133.97,4981.99 4145.47,4981.99 4155.97,4992.49 JP3.2@4243.97,4992.49 4296.49,4992.49 4316.25,5012.25 4401.5,5012.25 v4(4578.53,5012.23) 4599,4991.76 5160.68,4991.76 5166.7,4985.74 5210.64,4985.74 C6.2@5210.73,4985.83 ; v4(4578.64,5692.93) 4611.2,5725.49 J1.24@5037.91,5725.49
  Bottom Layer w6: v3(4401.97,5012.49) 4401.97,4180.23 4554.79,4027.41 4554.79,3514.43 v2(4552.55,3512.19)
  Bottom Layer w20: JP3.2@4243.97,4992.49 4244.82,4993.34 JP3.2@4244.82,5013.03 ; JP1.1@4244.82,5130.95 JP3.2@4244.82,5013.03 ; JP3.2@4245.6,5012.26 JP3.2@4244.82,5013.03 ; v4(4578.53,5012.23) 4578.53,5525.21 J3.8@4577.93,5525.82 4577.93,5692.22 v4(4578.64,5692.93)
pads on no net: CN6.A8 CN6.B8 J4.1 J4.8 R37.2 U6.2 U6.3 U6.4 U6.5 U6.6 U6.14 U6.15 U6.16 U6.17 U6.18 U6.21 U6.22 U6.29 U6.33 U6.38 U6.41 U6.42 U6.43 U6.45 U6.46
copper on no net: | length 1662.9
  Top Layer w6: 3373.92,5556.16 3399.92,5530.16 3399.92,5519.55 3391.92,5511.55 v1(3391.92,5501.82) ; v2(3419.92,4281.82) 3437.78,4299.68 3437.78,4398.38
  Bottom Layer w6: v1(3391.92,5501.82) 3391.92,5491.42 3397.92,5485.42 3397.92,5188.79 3213.1,5003.96 3213.1,4350.64 3287.92,4275.82 3413.92,4275.82 v2(3419.92,4281.82)

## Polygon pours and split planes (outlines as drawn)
GND on Top Layer (solid, remove dead copper): 3017.5,3031.29 6579.45,3031.29 6579.45,6117.4 3017.5,6117.4
GND on Bottom Layer (solid, remove dead copper, pour order 2): 3000,3000 6538.04,3000 6538.04,6103.45 3000,6103.45

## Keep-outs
Top Layer:
  region: 4077.97,4490.49 4127.97,4490.49 4127.97,4526.49 4077.97,4526.49
  region: 4091.97,4670.49 4121.97,4670.49 4121.97,4702.49 4091.97,4702.49
Board Outline Layer:
  lines w7.99: 3777.67,5691.27 3777.67,6007.93 ; 3777.93,3143.53 3777.93,3593.21 ; 3777.93,3666.27 3777.93,3758.27 ; 3777.93,3869.27 3777.93,4885.27 ; 3777.93,4963.27 3777.93,5613.27 ; 3816.93,3143.47 3816.93,3593.21 ; 3816.93,3666.27 3816.93,3758.27 ; 3816.93,3869.27 3816.93,4885.27 ; 3816.93,4963.27 3816.93,5613.27 ; 3817.19,5691.27 3817.19,6016.48
  lines w8: 3698.93,6086.67 cw(c3698.93,6007.93) 3777.67,6007.93 ; 3699.32,3065.55 ccw(c3699.32,3144.29) 3778.06,3144.29 ; 3777.67,5691.27 3817.19,5691.27 ; 3777.93,3593.21 3816.93,3593.21 ; 3777.93,3666.27 3816.93,3666.27 ; 3777.93,3758.27 3816.93,3758.27 ; 3777.93,3869.27 3816.93,3869.27 ; 3777.93,4885.27 3816.93,4885.27 ; 3777.93,4963.27 3816.93,4963.27 ; 3777.93,5613.27 3816.93,5613.27 ; 3816.88,3144.41 ccw(c3895.84,3144.41) 3895.84,3065.45 ; 3817.19,6007.93 cw(c3895.93,6007.93) 3895.93,6086.67 ; 6442.17,3065.43 ccw(c6442.17,3138.94) 6515.68,3138.94 ; 3049.97,3143.23 ccw(c3128.71,3143.23) 3128.71,3064.49 6437.23,3064.49 ccw(c6437.23,3143.23) 6515.97,3143.23 6515.97,6007.75 ccw(c6437.23,6007.75) 6437.23,6086.49 3128.71,6086.49 ccw(c3128.71,6007.75) 3049.97,6007.75 3049.97,3143.23
Multi-Layer:
  circle w10: c6392.13,5962.67 r62.99
  circle w10: c6392.13,3187.98 r62.99
  circle w10: c3940.93,3187.98 r62.99
  circle w10: c4187.27,3626.35 r62.99
  circle w10: c6237.27,4926.35 r62.99
  circle w10: c4237.27,5526.35 r62.99
  circle w10: c3940.94,5962.67 r62.99

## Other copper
Top Layer:
  drawing of 553 lines, arcs and shapes, not listed
Bottom Layer:
  drawing of 316 lines, arcs and shapes, not listed

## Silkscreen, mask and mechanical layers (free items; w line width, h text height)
Top Silkscreen Layer:
  region: 6039.97,5404.49 6019.97,5384.49 6059.97,5384.49
  region: 6119.97,5404.49 6159.97,5404.49 6139.97,5384.49
  lines w6: 3261.92,3350.82 3261.92,3649.82 ; 3361.98,3351.1 3361.98,3649.82 ; 3461.98,3350.79 3461.98,3649.82 ; 3561.98,3350.79 3561.98,3649.82 ; 4107.12,4227.77 4072.95,4261.95 4072.95,4193.36 4107.25,4227.65 ; 4127.67,3979.66 4091.45,3979.66 4091.45,4074.27 4127.67,4074.27
  lines w8: 3362.92,3276.1 3362.92,3315.73 3463.92,3315.73 3463.92,3275.1 ; 3651.92,3343.82 3575.92,3343.82 3614.92,3304.82 3652.92,3342.82
  lines w10: 4749.97,5244.49 6179.97,5244.49 ; 5017.51,3918.99 5470.51,3918.99 ; 5608.94,3919.13 6168.94,3919.13 ; 5860.2,4144.17 6140.2,4144.17 ; 5860.33,4044.47 6140.33,4044.47 ; 5860.33,4244.29 6140.33,4244.29
  text "25" at 6103.87,5996.51 h55.07
  text "47" at 5000.04,5996.11 h55.47
  text "41" at 5310.44,5996.11 h55.47
  text "31" at 5806.59,5996.11 h55.47
  text "A12" at 5715.61,5879.93 h61.63 r45
  text "B8" at 5128.23,5879.32 h61.63 r45
  text "A8" at 5921.77,5878.8 h61.63 r45
  text "B14" at 6019.36,5879.12 h61.63 r45
  text "F6" at 5630.01,5878.43 h61.63 r45
  text "A10" at 5817.99,5877.93 h61.63 r45
  text "B12" at 6119.36,5878.45 h61.63 r45
  text "B7" at 5230.75,5877.32 h61.63 r45
  text "B5" at 5327.8,5877.32 h61.63 r45
  text "B3" at 5425.16,5877.32 h61.63 r45
  text "A14" at 5519.28,5876.6 h61.63 r45
  text "GND" at 5015.63,5872.53 h61.63 r45
  text "GND" at 4079.97,5812.49 h73.96
  text "BOOT0 /  /F11" at 5178.44,5580.74 h43
  text "B4" at 5445.06,5575.84 h61.63 r45
  text "F7" at 5646.15,5574.94 h61.63 r45
  text "B9" at 5137.06,5574.49 h61.63 r45
  text "B6" at 5343.63,5574.49 h61.63 r45
  text "A9" at 5945.3,5573.97 h61.63 r45
  text "B15" at 6040.55,5568.9 h58.55 r45
  text "B13" at 6138.4,5568.9 h58.55 r45
  text "A15" at 5536.19,5568.18 h58.55 r45
  text "A13" at 5737.52,5568.18 h58.55 r45
  text "A11" at 5840.91,5567.71 h61.63 r45
  text "VDD" at 5029.31,5559.51 h59 r45
  text "4" at 5779.35,5415.97 h73.42 r90
  text "8" at 5318.35,5414.97 h73.42 r90
  text "7" at 5482.35,5414.97 h73.42 r90
  text "2" at 5976.35,5414.97 h73.42 r90
  text "13" at 4816.64,5375.96 h73.96 r90
  text "12" at 4916.64,5375.96 h73.96 r90
  text "#6" at 5578.64,5369.96 h73.96 r90
  text "#5" at 5679.64,5369.96 h73.96 r90
  text "#9" at 5217.64,5368.96 h73.96 r90
  text "#3" at 5878.64,5368.96 h73.96 r90
  text "#11" at 5016.64,5331.07 h73.96 r90
  text "#10" at 5117.64,5331.07 h73.96 r90
  text "SCL" at 4416.64,5321.07 h73.96 r90
  text "SDA" at 4516.64,5321.07 h73.96 r90
  text "GND" at 4717.35,5321.07 h73.96 r90
  text "GND" at 4007.97,5280.49 h74
  text "TX 1" at 6079.64,5278.17 h73.96 r90
  text "RX 0" at 6180.64,5278.17 h73.96 r90
  text "VDDA" at 4617.35,5276.17 h73.96 r90
  text "DIGITAL(#=PWM)" at 5177.51,5256.55 h73.96
  text "LD:" at 3680.94,5227.86 h55.47 r270
  text "BOOT0" at 3943.46,5185.41 h73.96
  text "1" at 3683.33,5114.63 h55.07 r270
  text "VDD" at 4009.97,5096.49 h74
  text "AT-Link-EZ V1.4" at 3073.16,5092.28 h90 r270
  text "2" at 3682.33,5047.63 h55.07 r270
  text "3" at 3681.33,4974.63 h55.07 r270
  text "IDD" at 4325.97,4908.49 h73.96
  text "4" at 3682.33,4899.63 h55.07 r270
  text "5V" at 6329.62,4687.66 h73.96
  text "MISO" at 5910.84,4684.48 h73.96
  text "MOSI" at 6334.38,4587.45 h73.96
  text "SCK" at 5913.3,4585.9 h73.96
  text "RESET" at 5862.14,4487.32 h73.96
  text "GND" at 6331.73,4487.23 h73.96
  text "NSS" at 5915.23,4388.73 h73.96
  text "PB11" at 6333.84,4387.56 h73.96
  text "AT-Link" at 4104.97,4289.49 h74
  text "3V3" at 6022.3,4264.75 h54
  text "3V3" at 3904.86,4184.27 h72
  text "E5V" at 4348.86,4182.27 h72
  text "USART1_TX" at 5829.64,4163.6 h54
  text "BOOT0" at 4348.86,4088.27 h72
  text "SWDIO" at 3858.06,4084.27 h72
  text "USART1_RX" at 5829.64,4068.7 h54
  text "AT-START-M412 V1.0" at 4605.08,4012.49 h110
  text "SWCLK" at 3835.26,3990.27 h72
  text "SWO" at 4348.86,3984.27 h72
  text "GND" at 6023.8,3968.59 h54
  text "NRST" at 3894.86,3890.27 h72
  text "USART1_RX" at 4348.86,3884.27 h72
  text "POWER" at 5249.11,3838.17 h73.96
  text "ANALOG IN" at 5773.69,3837.72 h73.96
  text "GND" at 3942.86,3786.27 h72
  text "USART1_TX" at 4348.86,3784.27 h72
  text "IOREF" at 4879.34,3709.13 h73.96 r90
  text "RESET" at 4979.34,3709.13 h73.96 r90
  text "3.3V" at 5077.35,3707.17 h73.96 r90
  text "VIN" at 5481.34,3704.92 h73.96 r90
  text "AN0" at 5674.34,3704.92 h73.96 r90
  text "AN1" at 5774.34,3704.92 h73.96 r90
  text "AN2" at 5875.35,3705.07 h73.96 r90
  text "AN3" at 5974.34,3704.92 h73.96 r90
  text "AN4" at 6074.34,3704.92 h73.96 r90
  text "AN5" at 6174.34,3704.92 h73.96 r90
  text "5V" at 5177.35,3702.96 h73.96 r90
  text "GND" at 5284.34,3697.92 h73.96 r90
  text "GND" at 5386.34,3697.92 h73.96 r90
  text "SWC" at 3371.87,3642.24 h64.72 r270
  text "GND" at 3180.56,3641.23 h64.72 r270
  text "SWD" at 3470.49,3641.1 h64.72 r270
  text "3V3" at 3577.12,3640.09 h64.72 r270
  text "NRST" at 3278.56,3636.39 h64.72 r270
  text "F1*" at 5225.63,3486.37 h54 r45
  text "B0" at 5831.08,3484.65 h61.63 r45
  text "F9" at 5332.07,3484.07 h61.63 r45
  text "B2" at 5928.11,3482.65 h61.63 r45
  text "A4" at 5622.52,3480.81 h61.63 r45
  text "A6" at 5723.12,3481.46 h61.63 r45
  text "BOOT0" at 3472.39,3479.76 h58 r270
  text "A0" at 5421.39,3480.13 h61.63 r45
  text "A2" at 5522.89,3480.13 h61.63 r45
  text "B11" at 6023.8,3477.72 h61.63 r45
  text "F13" at 6118.02,3474 h61.63 r45
  text "GND" at 6331.97,3474.49 h73.96
  text "C13" at 5016.78,3472.5 h58.55 r45
  text "C15*" at 5113.07,3472.5 h54 r45
  text "E5V" at 3575.06,3470.68 h64.72 r270
  text "SWO" at 3377.61,3466.8 h64.72 r270
  text "RX" at 3179.67,3455.67 h64.72 r270
  text "TX" at 3278.56,3455.7 h64.72 r270
  text "B1" at 5946.08,3177.81 h61.63 r45
  text "A1" at 5542.66,3175.33 h61.63 r45
  text "F8" at 5046.53,3171.66 h61.63 r45
  text "F10" at 5443.38,3170.38 h61.63 r45
  text "A5" at 5747.4,3166.71 h61.63 r45
  text "A3" at 5642.84,3165.5 h61.63 r45
  text "F0*" at 5221.45,3163.76 h54 r45
  text "A7" at 5846.02,3164.23 h61.63 r45
  text "B10" at 6041.77,3164.44 h55.47 r45
  text "C14*" at 5127.53,3162.12 h54 r45
  text "NRST /  /F2" at 5285.51,3157.74 h50
  text "PF12" at 6142.01,3154.54 h55.47 r45
  text "USER" at 4636.7,3143.17 h73.96
  text "RESET" at 4164.54,3142.45 h73.96
  text "1" at 5032.37,3095.66 h55.47
  text "11" at 5521.33,3095.66 h55.47
  text "21" at 6015.45,3095.66 h55.47
  text "23" at 6111.37,3095.66 h55.47
Bottom Silkscreen Layer:
  text "31" at 5840.45,5872.12 h60 r315
  text "29" at 5948.11,5871.48 h60 r315
  text "39" at 5443.44,5869.68 h60 r315
  text "25" at 6146.66,5869.71 h60 r315
  text "41" at 5340.54,5869.15 h60 r315
  text "27" at 6046.13,5868.55 h60 r315
  text "35" at 5648.38,5867.91 h60 r315
  text "37" at 5545.65,5866.74 h60 r315
  text "33" at 5749.1,5867.34 h60 r315
  text "45" at 5145.75,5864.94 h60 r315
  text "47" at 5048.66,5863.77 h60 r315
  text "43" at 5248.83,5864.37 h60 r315
  text "42" at 5338.67,5594.37 h60 r315
  text "48" at 5035.67,5593.37 h60 r315
  text "46" at 5136.67,5593.37 h60 r315
  text "44" at 5235.67,5593.37 h60 r315
  text "40" at 5437.67,5593.37 h60 r315
  text "38" at 5533.67,5593.37 h60 r315
  text "36" at 5633.67,5593.37 h60 r315
  text "34" at 5734.67,5593.37 h60 r315
  text "32" at 5836.67,5593.37 h60 r315
  text "30" at 5935.67,5593.37 h60 r315
  text "28" at 6036.67,5593.37 h60 r315
  text "26" at 6139.67,5593.37 h60 r315
  text "VDD" at 3716.4,4911.56 h55.47 r90
  text "VDD" at 3589,4252.33 h55.47
  text "AT32M412CBT7" at 5703.97,4214.14 h184.9
  text "M-SWDIO" at 3584.22,4154.43 h55.47
  text "M-SWCLK" at 3584.22,4054.43 h55.47
  text "M-NRST" at 3585.8,3954.43 h55.47
  text "GND" at 3590.55,3854.43 h55.47
  text "2" at 5029.36,3478.96 h60 r315
  text "6" at 5229.36,3476.55 h60 r315
  text "8" at 5329.58,3476.55 h60 r315
  text "4" at 5133.36,3474.82 h60 r315
  text "10" at 5435.58,3468.03 h60 r315
  text "12" at 5538.58,3468.03 h60 r315
  text "14" at 5639.58,3468.07 h60 r315
  text "16" at 5741.58,3468.03 h60 r315
  text "24" at 6145.58,3467.66 h60 r315
  text "18" at 5838.58,3467.43 h60 r315
  text "20" at 5941.58,3465.63 h60 r315
  text "22" at 6043.58,3465.63 h60 r315
  text "1" at 5017.73,3217.67 h60 r315
  text "9" at 5423.91,3216.54 h60 r315
  text "5" at 5227.85,3214.91 h60 r315
  text "3" at 5124.24,3214.38 h60 r315
  text "7" at 5322.48,3213.25 h60 r315
  text "11" at 5526.57,3210.17 h60 r315
  text "19" at 5929.57,3208.02 h60 r315
  text "13" at 5627.57,3205.83 h60 r315
  text "15" at 5732.57,3206.36 h60 r315
  text "17" at 5830.57,3205.26 h60 r315
  text "21" at 6032.57,3203.98 h60 r315
  text "23" at 6132.57,3197.63 h60 r315
Mechanical Layer:
  circle w1: c6392.13,5962.67 r62.99
  circle w1: c6392.13,3187.98 r62.99
  circle w1: c3940.93,3187.98 r62.99
  circle w1: c4187.27,3626.35 r62.99
  circle w1: c6237.27,4926.35 r62.99
  circle w1: c4237.27,5526.35 r62.99
  circle w1: c3940.94,5962.67 r62.99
